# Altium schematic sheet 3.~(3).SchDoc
size 420 x 297 mm
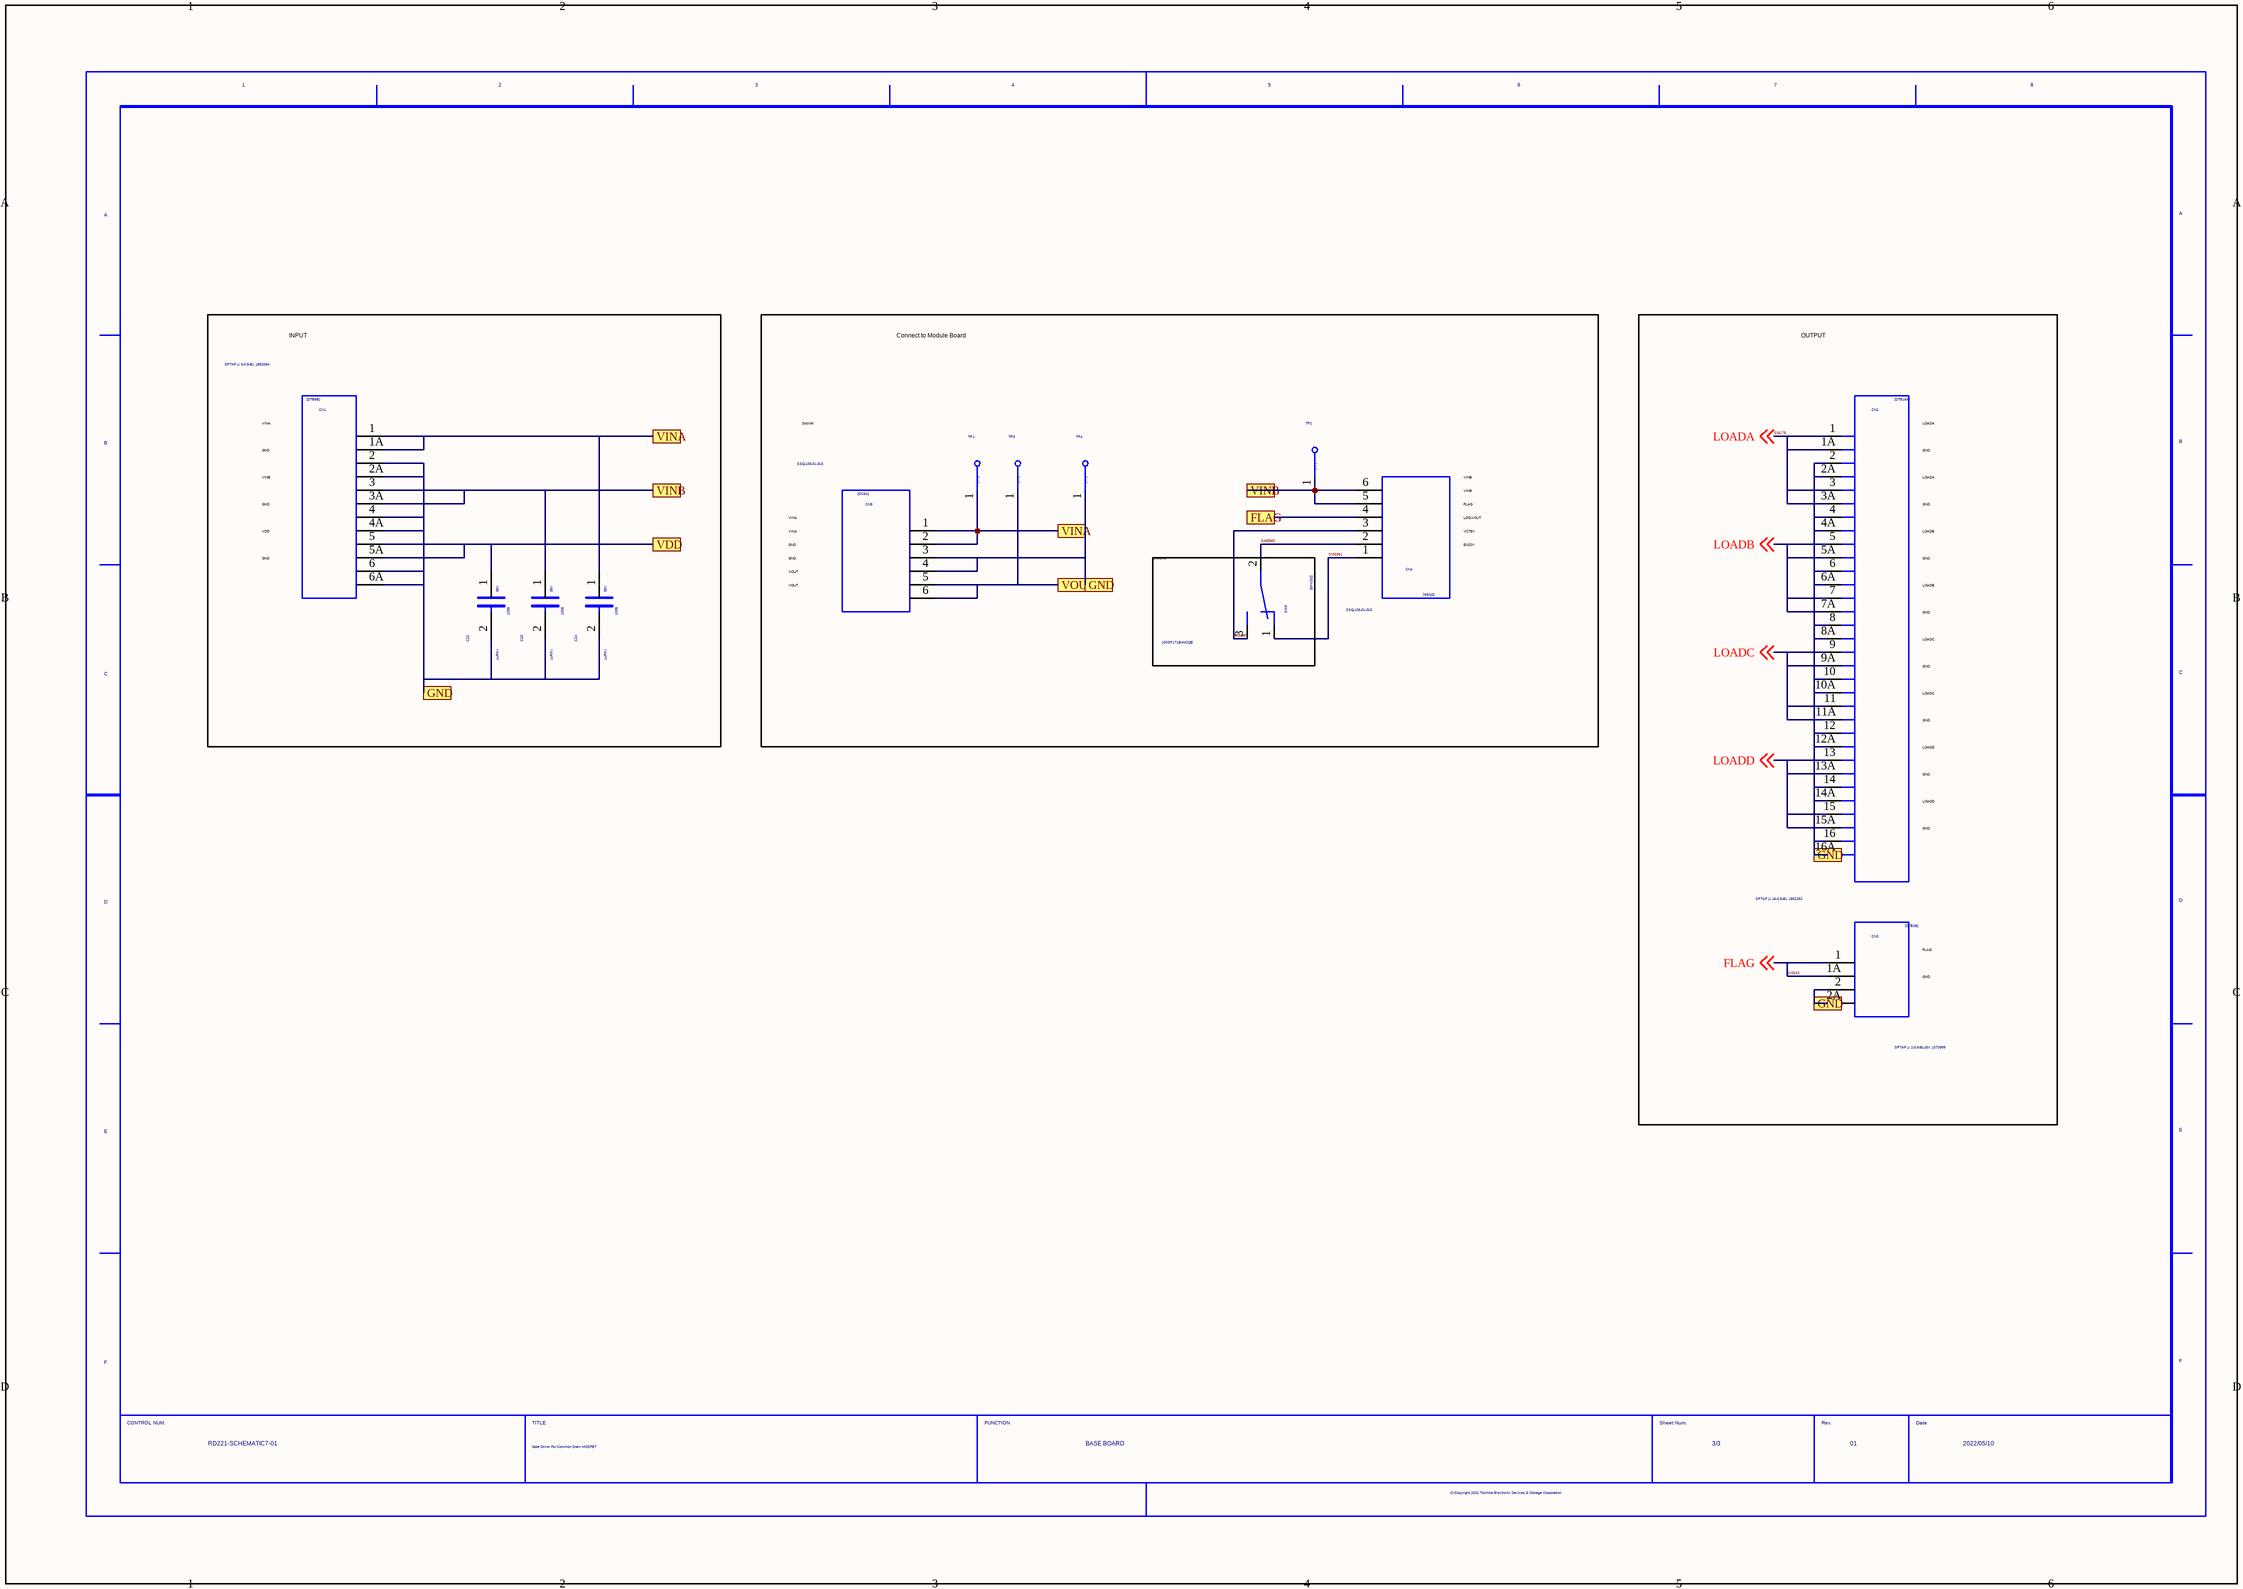
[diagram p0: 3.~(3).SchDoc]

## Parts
C22  SIZECODESMD: 1005  VAL2: 35V  VAL1: 1uF(K)  (hidden comment: DC)
C23  SIZECODESMD: 1005  VAL2: 35V  VAL1: 1uF(K)  (hidden comment: DC)
C24  SIZECODESMD: 1005  VAL2: 35V  VAL1: 1uF(K)  (hidden comment: DC)
CN1  VAL3: SPTAF 1/ 6-3,5-EL 1862084  (hidden comment: DTB6B)
CN2  VAL3: SPTAF 1/ 16-3,5-EL 1862262  (hidden comment: DTB16A)
CN3  VAL3: SPTAF 1/ 2-3,5-EL-EX 1070999  (hidden comment: DTB2B)
CN4  VAL3: SSQ-106-01-G-S  (hidden comment: DC6A)
CN5  VAL3: SSQ-106-01-G-S  (hidden comment: DC6A)
SW6  VAL3: 100SP1T1B4M2QE  (hidden comment: DSW49)
TP1  DTP  (value not drawn)
TP2  DTP  (value not drawn)
TP3  DTP  (value not drawn)
TP4  DTP  (value not drawn)
U?  DATE: 2022/05/10  REVISION: 01  SHEETNUMBER: 3/3  FUNCTION: BASE BOARD  TITLE: Gate Driver For Common Drain MOSFET  DRAWINGNUMBER: RD221-SCHEMATIC7-01  (hidden comment: WAKU_DEF100)

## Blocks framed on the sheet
INPUT: C22-C24 CN1
Connect to Module Board: CN4 CN5 TP1-TP4
OUTPUT: CN2 CN3
Switch6: SW6

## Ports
FLAG, GND, VDD, VINA, VINB, VOUT

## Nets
GND: C22.2 C23.2 C24.1 C24.2 CN1.1 CN1.1A CN1.2 CN1.2A CN1.4 CN1.4A CN1.6 CN1.6A CN2.2 CN2.2A CN2.4 CN2.4A CN2.6 CN2.6A CN2.8 CN2.8A CN2.10 CN2.10A CN2.12 CN2.12A CN2.14 CN2.14A CN2.16 CN2.16A CN3.2 CN3.2A CN5.1 CN5.2 CN5.3 CN5.4 CN5.5 CN5.6 TP1.1 TP3.1 TP4.1 ; port GND, port VINA, port VOUT
LOADB: CN2.5 CN2.5A CN2.7 CN2.7A ; off-sheet LOADB
LOADC: CN2.9 CN2.9A CN2.11 CN2.11A ; off-sheet LOADC
LOADD: CN2.13 CN2.13A CN2.15 CN2.15A ; off-sheet LOADD
SIG175: CN2.1 CN2.1A CN2.3 CN2.3A ; off-sheet LOADA  [also labelled LOADA]
SIG213: CN3.1 CN3.1A CN4.4 ; off-sheet FLAG, port FLAG  [also labelled FLAG]
SIG3359: CN4.3 SW6.3
SIG3360: CN4.2 SW6.2
SIG3361: CN4.1 SW6.1
VDD: C22.1 CN1.5 CN1.5A ; port VDD
VINB: C23.1 CN1.3 CN1.3A CN4.5 CN4.6 TP2.1 ; port VINB

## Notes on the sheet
- VINA
- GND
- Socket
- LOADA
- VINB
- VDD
- FLAG
- LDO-VOUT
- VCT5V
- LOADB
- VOUT
- EN20V
- LOADC
- LOADD

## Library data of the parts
C22-C24 = DC: OUMEPARTTYPE: C; OriginalSymbolOrigin: (2540,7620); COMPONENTNAME: DP0000016125_package; MAXGCOUNT: 1; COMP: DP0000016125; VAL3: GRM155R6YA105KE11D
CN1 = DTB6B: OUMEPARTTYPE: TB; SAVEAREA0: -69082,-11475,84961,51811; TIME: 10:12:24; UPDATEUSER: w90028dm; UPDATETIME: 11:01:53; SAVECOUNT: 6; OriginalSymbolOrigin: (0,38100); COMPONENTNAME: DP0010576000_package; MAXGCOUNT: 1; COMP: DP0010576000
CN2 = DTB16A: OUMEPARTTYPE: TB; SAVEAREA0: -110709,-1964,126601,95531; TIME: 12:01:18; UPDATEUSER: w90028dm; UPDATETIME: 09:06:25; SAVECOUNT: 20; OriginalSymbolOrigin: (0,91440); COMPONENTNAME: DP0010577000_package; MAXGCOUNT: 1; COMP: DP0010577000
CN3 = DTB2B: OUMEPARTTYPE: TB; SAVEAREA0: -49339,-13811,66103,33616; TIME: 10:12:24; UPDATEUSER: w90028dm; UPDATETIME: 11:01:13; SAVECOUNT: 5; OriginalSymbolOrigin: (0,17780); COMPONENTNAME: DP0010578000_package; MAXGCOUNT: 1; COMP: DP0010578000
CN4 CN5 = DC6A: OUMEPARTTYPE: CN; SAVEAREA0: -19103,0,39483,27940; SAVECOUNT: 24; TIME: 13:28:28; UPDATEUSER: e1023210; UPDATETIME: 18:37:18; OriginalSymbolOrigin: (2540,25400); COMPONENTNAME: DP0010574000_package; MAXGCOUNT: 1; COMP: DP0010574000
SW6 = DSW49: OUMEPARTTYPE: S; SAVEAREA0: -42205,-15236,59041,26359; TIME: 14:45:03; UPDATEUSER: w90028dm; UPDATETIME: 17:53:32; SAVECOUNT: 4; OriginalSymbolOrigin: (2540,10160); COMPONENTNAME: DP0010575000_package; MAXGCOUNT: 1; COMP: DP0010575000
TP1-TP4 = DTP: OUMEPARTTYPE: TP; TIME: 16:12:21; UPDATEUSER: fukuda-y; UPDATETIME: 16:18:11; SAVECOUNT: 2; SAVEAREA0: -242,-92,12810,7836; OriginalSymbolOrigin: (0,7620); NOTMOUNT: NOT MOUNT; COMPONENTNAME: DP9000817000_package; MAXGCOUNT: 1; COMP: DP9000817000
U? = WAKU_DEF100: PLOTTIME: HH:MM; SAVEAREA0: 148187,-66180,486823,89919; TIME: 14:30:25; UPDATEUSER: t5459927; UPDATETIME: 18:03:24; SAVECOUNT: 6; OriginalSymbolOrigin: (10160,284480)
